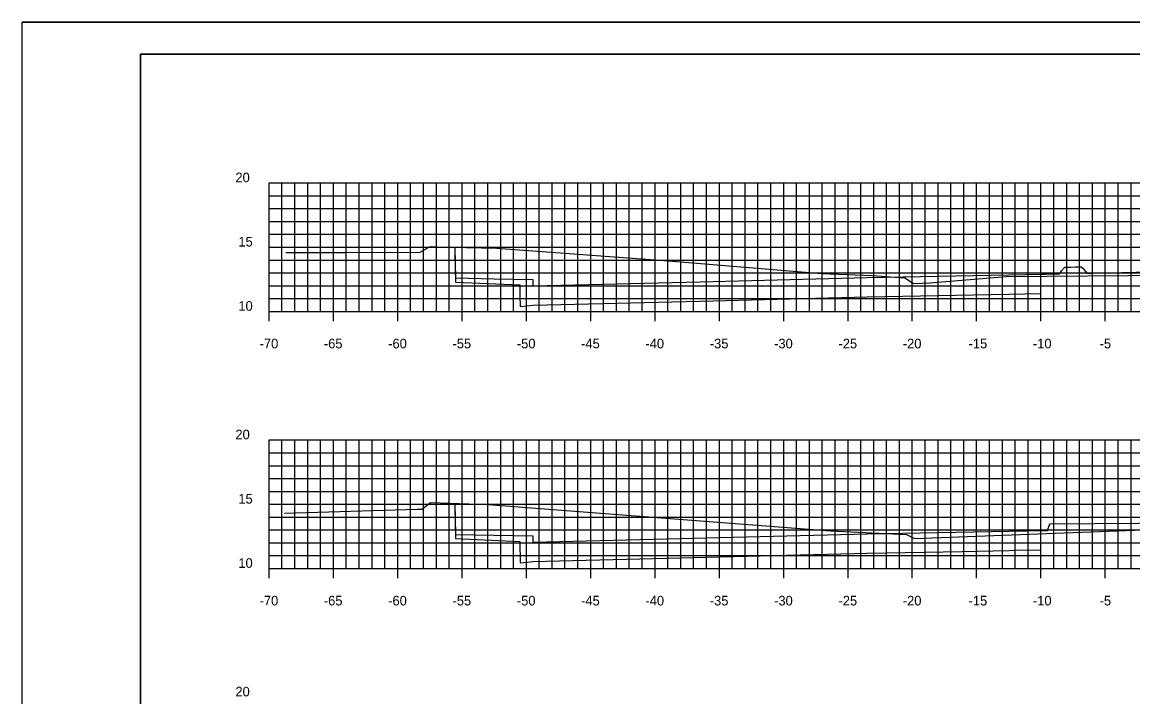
# Model space of a CAD drawing. Extents: x 40011 to 50684, y 49949 to 72236.
# Drawn here: x 40019.3 to 40105.6, y 71631.7 to 71684.2 of the extents above; entities that cross this region are included whole.
import ezdxf

# ---------------------------------------------------------------- set-up
doc = ezdxf.new("R2010")
doc.units = 0
for name, color, linetype in [('1', 7, 'Continuous'), ('41', 7, 'Continuous'), ('51', 7, 'Continuous'), ('52', 7, 'Continuous'), ('53', 7, 'Continuous'), ('54', 7, 'Continuous'), ('55', 7, 'Continuous'), ('57', 7, 'Continuous'), ('58', 7, 'Continuous'), ('59', 7, 'Continuous')]:
    doc.layers.add(name, color=color, linetype=linetype)

msp = doc.modelspace()

# ---------------------------------------------------------------- linework, layer by layer
at = {"layer": '1'}
for p, q in [((40193.946, 71684.191), (40019.252, 71684.191)), ((40028.446, 71681.691), (40028.446, 71576.691)), ((40193.446, 71681.691), (40028.446, 71681.691))]:
    msp.add_line(p, q, dxfattribs=at)
at = {"layer": '41'}
for points in [[(40019.252, 71684.191), (40193.946, 71684.191), (40193.946, 71574.191), (40019.252, 71574.191)], [(40028.446, 71681.691), (40193.446, 71681.691), (40193.446, 71576.691), (40028.446, 71576.691)]]:
    msp.add_lwpolyline(points, close=True, dxfattribs=at)
at = {"layer": '51'}
for p, q in [((40038.446, 71661.691), (40038.446, 71671.691)), ((40038.446, 71671.691), (40039.196, 71671.691)), ((40038.446, 71666.691), (40039.196, 71666.691)), ((40038.446, 71661.691), (40039.196, 71661.691)), ((40038.446, 71641.691), (40038.446, 71651.691)), ((40038.446, 71651.691), (40039.196, 71651.691)), ((40038.446, 71646.691), (40039.196, 71646.691)), ((40038.446, 71641.691), (40039.196, 71641.691))]:
    msp.add_line(p, q, dxfattribs=at)
at = {"layer": '52'}
for p, q in [((40038.446, 71661.691), (40178.446, 71661.691)), ((40038.446, 71660.941), (40038.446, 71661.691)), ((40043.446, 71660.941), (40043.446, 71661.691)), ((40048.446, 71660.941), (40048.446, 71661.691)), ((40053.446, 71660.941), (40053.446, 71661.691)), ((40058.446, 71660.941), (40058.446, 71661.691)), ((40063.446, 71660.941), (40063.446, 71661.691)), ((40068.446, 71660.941), (40068.446, 71661.691)), ((40073.446, 71660.941), (40073.446, 71661.691)), ((40078.446, 71660.941), (40078.446, 71661.691)), ((40083.446, 71660.941), (40083.446, 71661.691)), ((40088.446, 71660.941), (40088.446, 71661.691)), ((40093.446, 71660.941), (40093.446, 71661.691)), ((40098.446, 71660.941), (40098.446, 71661.691)), ((40103.446, 71660.941), (40103.446, 71661.691)), ((40038.446, 71641.691), (40178.446, 71641.691)), ((40038.446, 71640.941), (40038.446, 71641.691)), ((40043.446, 71640.941), (40043.446, 71641.691)), ((40048.446, 71640.941), (40048.446, 71641.691)), ((40053.446, 71640.941), (40053.446, 71641.691)), ((40058.446, 71640.941), (40058.446, 71641.691)), ((40063.446, 71640.941), (40063.446, 71641.691)), ((40068.446, 71640.941), (40068.446, 71641.691)), ((40073.446, 71640.941), (40073.446, 71641.691)), ((40078.446, 71640.941), (40078.446, 71641.691)), ((40083.446, 71640.941), (40083.446, 71641.691)), ((40088.446, 71640.941), (40088.446, 71641.691)), ((40093.446, 71640.941), (40093.446, 71641.691)), ((40098.446, 71640.941), (40098.446, 71641.691)), ((40103.446, 71640.941), (40103.446, 71641.691))]:
    msp.add_line(p, q, dxfattribs=at)
at = {"layer": '53'}
for p, q in [((40038.446, 71670.691), (40178.446, 71670.691)), ((40038.446, 71669.691), (40178.446, 71669.691)), ((40038.446, 71668.691), (40178.446, 71668.691)), ((40038.446, 71667.691), (40178.446, 71667.691)), ((40038.446, 71665.691), (40178.446, 71665.691)), ((40038.446, 71664.691), (40178.446, 71664.691)), ((40038.446, 71663.691), (40178.446, 71663.691)), ((40038.446, 71662.691), (40178.446, 71662.691)), ((40038.446, 71650.691), (40178.446, 71650.691)), ((40038.446, 71649.691), (40178.446, 71649.691)), ((40038.446, 71648.691), (40178.446, 71648.691)), ((40038.446, 71647.691), (40178.446, 71647.691)), ((40038.446, 71645.691), (40178.446, 71645.691)), ((40038.446, 71644.691), (40178.446, 71644.691)), ((40038.446, 71643.691), (40178.446, 71643.691)), ((40038.446, 71642.691), (40178.446, 71642.691))]:
    msp.add_line(p, q, dxfattribs=at)
at = {"layer": '54'}
for p, q in [((40039.446, 71661.691), (40039.446, 71671.691)), ((40040.446, 71661.691), (40040.446, 71671.691)), ((40041.446, 71661.691), (40041.446, 71671.691)), ((40042.446, 71661.691), (40042.446, 71671.691)), ((40044.446, 71661.691), (40044.446, 71671.691)), ((40045.446, 71661.691), (40045.446, 71671.691)), ((40046.446, 71661.691), (40046.446, 71671.691)), ((40047.446, 71661.691), (40047.446, 71671.691)), ((40049.446, 71661.691), (40049.446, 71671.691)), ((40050.446, 71661.691), (40050.446, 71671.691)), ((40051.446, 71661.691), (40051.446, 71671.691)), ((40052.446, 71661.691), (40052.446, 71671.691)), ((40054.446, 71661.691), (40054.446, 71671.691)), ((40055.446, 71661.691), (40055.446, 71671.691)), ((40056.446, 71661.691), (40056.446, 71671.691)), ((40057.446, 71661.691), (40057.446, 71671.691)), ((40059.446, 71661.691), (40059.446, 71671.691)), ((40060.446, 71661.691), (40060.446, 71671.691)), ((40061.446, 71661.691), (40061.446, 71671.691)), ((40062.446, 71661.691), (40062.446, 71671.691)), ((40064.446, 71661.691), (40064.446, 71671.691)), ((40065.446, 71661.691), (40065.446, 71671.691)), ((40066.446, 71661.691), (40066.446, 71671.691)), ((40067.446, 71661.691), (40067.446, 71671.691)), ((40069.446, 71661.691), (40069.446, 71671.691)), ((40070.446, 71661.691), (40070.446, 71671.691)), ((40071.446, 71661.691), (40071.446, 71671.691)), ((40072.446, 71661.691), (40072.446, 71671.691)), ((40074.446, 71661.691), (40074.446, 71671.691)), ((40075.446, 71661.691), (40075.446, 71671.691)), ((40076.446, 71661.691), (40076.446, 71671.691)), ((40077.446, 71661.691), (40077.446, 71671.691)), ((40079.446, 71661.691), (40079.446, 71671.691)), ((40080.446, 71661.691), (40080.446, 71671.691)), ((40081.446, 71661.691), (40081.446, 71671.691)), ((40082.446, 71661.691), (40082.446, 71671.691)), ((40084.446, 71661.691), (40084.446, 71671.691)), ((40085.446, 71661.691), (40085.446, 71671.691)), ((40086.446, 71661.691), (40086.446, 71671.691)), ((40087.446, 71661.691), (40087.446, 71671.691)), ((40089.446, 71661.691), (40089.446, 71671.691)), ((40090.446, 71661.691), (40090.446, 71671.691)), ((40091.446, 71661.691), (40091.446, 71671.691)), ((40092.446, 71661.691), (40092.446, 71671.691)), ((40094.446, 71661.691), (40094.446, 71671.691)), ((40095.446, 71661.691), (40095.446, 71671.691)), ((40096.446, 71661.691), (40096.446, 71671.691)), ((40097.446, 71661.691), (40097.446, 71671.691)), ((40099.446, 71661.691), (40099.446, 71671.691)), ((40100.446, 71661.691), (40100.446, 71671.691)), ((40101.446, 71661.691), (40101.446, 71671.691)), ((40102.446, 71661.691), (40102.446, 71671.691)), ((40104.446, 71661.691), (40104.446, 71671.691)), ((40105.446, 71661.691), (40105.446, 71671.691)), ((40039.446, 71641.691), (40039.446, 71651.691)), ((40040.446, 71641.691), (40040.446, 71651.691)), ((40041.446, 71641.691), (40041.446, 71651.691)), ((40042.446, 71641.691), (40042.446, 71651.691)), ((40044.446, 71641.691), (40044.446, 71651.691)), ((40045.446, 71641.691), (40045.446, 71651.691)), ((40046.446, 71641.691), (40046.446, 71651.691)), ((40047.446, 71641.691), (40047.446, 71651.691)), ((40049.446, 71641.691), (40049.446, 71651.691)), ((40050.446, 71641.691), (40050.446, 71651.691)), ((40051.446, 71641.691), (40051.446, 71651.691)), ((40052.446, 71641.691), (40052.446, 71651.691)), ((40054.446, 71641.691), (40054.446, 71651.691)), ((40055.446, 71641.691), (40055.446, 71651.691)), ((40056.446, 71641.691), (40056.446, 71651.691)), ((40057.446, 71641.691), (40057.446, 71651.691)), ((40059.446, 71641.691), (40059.446, 71651.691)), ((40060.446, 71641.691), (40060.446, 71651.691)), ((40061.446, 71641.691), (40061.446, 71651.691)), ((40062.446, 71641.691), (40062.446, 71651.691)), ((40064.446, 71641.691), (40064.446, 71651.691)), ((40065.446, 71641.691), (40065.446, 71651.691)), ((40066.446, 71641.691), (40066.446, 71651.691)), ((40067.446, 71641.691), (40067.446, 71651.691)), ((40069.446, 71641.691), (40069.446, 71651.691)), ((40070.446, 71641.691), (40070.446, 71651.691)), ((40071.446, 71641.691), (40071.446, 71651.691)), ((40072.446, 71641.691), (40072.446, 71651.691)), ((40074.446, 71641.691), (40074.446, 71651.691)), ((40075.446, 71641.691), (40075.446, 71651.691)), ((40076.446, 71641.691), (40076.446, 71651.691)), ((40077.446, 71641.691), (40077.446, 71651.691)), ((40079.446, 71641.691), (40079.446, 71651.691)), ((40080.446, 71641.691), (40080.446, 71651.691)), ((40081.446, 71641.691), (40081.446, 71651.691)), ((40082.446, 71641.691), (40082.446, 71651.691)), ((40084.446, 71641.691), (40084.446, 71651.691)), ((40085.446, 71641.691), (40085.446, 71651.691)), ((40086.446, 71641.691), (40086.446, 71651.691)), ((40087.446, 71641.691), (40087.446, 71651.691)), ((40089.446, 71641.691), (40089.446, 71651.691)), ((40090.446, 71641.691), (40090.446, 71651.691)), ((40091.446, 71641.691), (40091.446, 71651.691)), ((40092.446, 71641.691), (40092.446, 71651.691)), ((40094.446, 71641.691), (40094.446, 71651.691)), ((40095.446, 71641.691), (40095.446, 71651.691)), ((40096.446, 71641.691), (40096.446, 71651.691)), ((40097.446, 71641.691), (40097.446, 71651.691)), ((40099.446, 71641.691), (40099.446, 71651.691)), ((40100.446, 71641.691), (40100.446, 71651.691)), ((40101.446, 71641.691), (40101.446, 71651.691)), ((40102.446, 71641.691), (40102.446, 71651.691)), ((40104.446, 71641.691), (40104.446, 71651.691)), ((40105.446, 71641.691), (40105.446, 71651.691))]:
    msp.add_line(p, q, dxfattribs=at)
at = {"layer": '55'}
for p, q in [((40038.446, 71671.691), (40178.446, 71671.691)), ((40038.446, 71661.691), (40038.446, 71671.691)), ((40043.446, 71661.691), (40043.446, 71671.691)), ((40048.446, 71661.691), (40048.446, 71671.691)), ((40053.446, 71661.691), (40053.446, 71671.691)), ((40058.446, 71661.691), (40058.446, 71671.691)), ((40063.446, 71661.691), (40063.446, 71671.691)), ((40068.446, 71661.691), (40068.446, 71671.691)), ((40073.446, 71661.691), (40073.446, 71671.691)), ((40078.446, 71661.691), (40078.446, 71671.691)), ((40083.446, 71661.691), (40083.446, 71671.691)), ((40088.446, 71661.691), (40088.446, 71671.691)), ((40093.446, 71661.691), (40093.446, 71671.691)), ((40098.446, 71661.691), (40098.446, 71671.691)), ((40103.446, 71661.691), (40103.446, 71671.691)), ((40038.446, 71666.691), (40178.446, 71666.691)), ((40038.446, 71661.691), (40178.446, 71661.691)), ((40038.446, 71651.691), (40178.446, 71651.691)), ((40038.446, 71641.691), (40038.446, 71651.691)), ((40043.446, 71641.691), (40043.446, 71651.691)), ((40048.446, 71641.691), (40048.446, 71651.691)), ((40053.446, 71641.691), (40053.446, 71651.691)), ((40058.446, 71641.691), (40058.446, 71651.691)), ((40063.446, 71641.691), (40063.446, 71651.691)), ((40068.446, 71641.691), (40068.446, 71651.691)), ((40073.446, 71641.691), (40073.446, 71651.691)), ((40078.446, 71641.691), (40078.446, 71651.691)), ((40083.446, 71641.691), (40083.446, 71651.691)), ((40088.446, 71641.691), (40088.446, 71651.691)), ((40093.446, 71641.691), (40093.446, 71651.691)), ((40098.446, 71641.691), (40098.446, 71651.691)), ((40103.446, 71641.691), (40103.446, 71651.691)), ((40038.446, 71646.691), (40178.446, 71646.691)), ((40038.446, 71641.691), (40178.446, 71641.691))]:
    msp.add_line(p, q, dxfattribs=at)
at = {"layer": '57'}
for points in [[(40039.748, 71666.271), (40044.426, 71666.284), (40050.174, 71666.299), (40050.175, 71666.3), (40050.908, 71666.725), (40051.376, 71666.714), (40056.148, 71666.607), (40069.502, 71665.637), (40081.38, 71664.64), (40085.316, 71664.486), (40087.849, 71664.305), (40087.85, 71664.305), (40087.868, 71664.296), (40088.535, 71663.862), (40089.81, 71663.904), (40095.747, 71664.404), (40108.401, 71664.512)], [(40039.63, 71646.003), (40049.955, 71646.305), (40050.32, 71646.317), (40050.972, 71646.802), (40050.994, 71646.82), (40055.484, 71646.664), (40080.745, 71644.734), (40082.079, 71644.632), (40087.988, 71644.33), (40088.576, 71644.058), (40088.652, 71644.014), (40108.458, 71644.784)]]:
    msp.add_lwpolyline(points, dxfattribs=at)
at = {"layer": '58'}
for points in [[(40052.888, 71666.359), (40052.913, 71665.093), (40052.936, 71663.965), (40055.438, 71663.857), (40057.94, 71663.749), (40057.946, 71662.915), (40057.951, 71662.08), (40058.448, 71662.127), (40058.946, 71662.174), (40071.946, 71662.499), (40084.946, 71662.824), (40090.447, 71662.934), (40095.946, 71663.044), (40098.441, 71663.093), (40098.446, 71663.093)], [(40052.888, 71646.424), (40052.936, 71644.019), (40055.739, 71643.898), (40057.941, 71643.803), (40057.95, 71642.134), (40058.53, 71642.188), (40058.946, 71642.227), (40084.946, 71642.877), (40092.319, 71643.025), (40095.946, 71643.097), (40096.4, 71643.106), (40098.446, 71643.147)]]:
    msp.add_lwpolyline(points, dxfattribs=at)
at = {"layer": '59'}
for points in [[(40052.888, 71666.689), (40052.914, 71665.423), (40052.936, 71664.295), (40055.936, 71664.235), (40058.936, 71664.175), (40058.941, 71663.925), (40058.946, 71663.675), (40071.946, 71664), (40084.946, 71664.325), (40090.446, 71664.435), (40095.946, 71664.545), (40098.547, 71664.597), (40098.593, 71664.598), (40098.65, 71664.599), (40098.718, 71664.6), (40098.797, 71664.602), (40098.888, 71664.603), (40098.99, 71664.606), (40099.103, 71664.608), (40099.226, 71664.61), (40099.358, 71664.613), (40099.497, 71664.616), (40099.643, 71664.619), (40099.794, 71664.622), (40099.884, 71664.623), (40099.932, 71664.692), (40099.953, 71664.722), (40100.048, 71664.842), (40100.11, 71664.921), (40100.158, 71664.974), (40100.254, 71665.079), (40100.31, 71665.131), (40100.748, 71665.141), (40101.116, 71665.149), (40101.245, 71665.151), (40101.31, 71665.153), (40101.35, 71665.154), (40101.376, 71665.154), (40101.395, 71665.155), (40101.41, 71665.155), (40101.421, 71665.155), (40101.463, 71665.156), (40101.547, 71665.158), (40101.555, 71665.158), (40101.56, 71665.158), (40101.567, 71665.158), (40101.574, 71665.158), (40101.584, 71665.159), (40101.724, 71665.02), (40101.8, 71664.931), (40101.883, 71664.834), (40102.008, 71664.666), (40102.051, 71664.667), (40102.21, 71664.67), (40102.361, 71664.673), (40102.503, 71664.676), (40106.946, 71664.765)], [(40052.888, 71646.754), (40052.936, 71644.349), (40058.936, 71644.229), (40058.946, 71643.729), (40084.946, 71644.379), (40095.946, 71644.599), (40098.946, 71644.659), (40099.136, 71645.16), (40106.061, 71645.214), (40110.756, 71645.25), (40110.946, 71644.751), (40113.946, 71644.706), (40124.946, 71644.486), (40139.946, 71644.111), (40139.956, 71644.611), (40146.956, 71644.751), (40147.157, 71644.684)]]:
    msp.add_lwpolyline(points, dxfattribs=at)

# ---------------------------------------------------------------- texts
at = {"layer": '51'}
for s, height, p in [('20', 0.75, (40035.826, 71671.741)), ('15', 0.75, (40036.053, 71666.741)), ('10', 0.75, (40036.053, 71661.741)), ('-', 0.0001, (40038.446, 71661.691)), ('20', 0.75, (40035.826, 71651.741)), ('15', 0.75, (40036.053, 71646.741)), ('10', 0.75, (40036.053, 71641.741)), ('-', 0.0001, (40038.446, 71641.691)), ('20', 0.75, (40035.826, 71631.741))]:
    msp.add_text(s, height=height, dxfattribs=at).set_placement(p)
at = {"layer": '52'}
for s, p in [('-70', (40037.707, 71658.816)), ('-65', (40042.701, 71658.816)), ('-60', (40047.701, 71658.816)), ('-55', (40052.703, 71658.816)), ('-50', (40057.703, 71658.816)), ('-45', (40062.698, 71658.816)), ('-40', (40067.698, 71658.816)), ('-35', (40072.702, 71658.816)), ('-30', (40077.702, 71658.816)), ('-25', (40082.707, 71658.816)), ('-20', (40087.707, 71658.816)), ('-15', (40092.82, 71658.816)), ('-10', (40097.82, 71658.816)), ('-5', (40103.005, 71658.816)), ('-70', (40037.707, 71638.816)), ('-65', (40042.701, 71638.816)), ('-60', (40047.701, 71638.816)), ('-55', (40052.703, 71638.816)), ('-50', (40057.703, 71638.816)), ('-45', (40062.698, 71638.816)), ('-40', (40067.698, 71638.816)), ('-35', (40072.702, 71638.816)), ('-30', (40077.702, 71638.816)), ('-25', (40082.707, 71638.816)), ('-20', (40087.707, 71638.816)), ('-15', (40092.82, 71638.816)), ('-10', (40097.82, 71638.816)), ('-5', (40103.005, 71638.816))]:
    msp.add_text(s, height=0.75, dxfattribs=at).set_placement(p)

doc.saveas('drawing.dxf')
